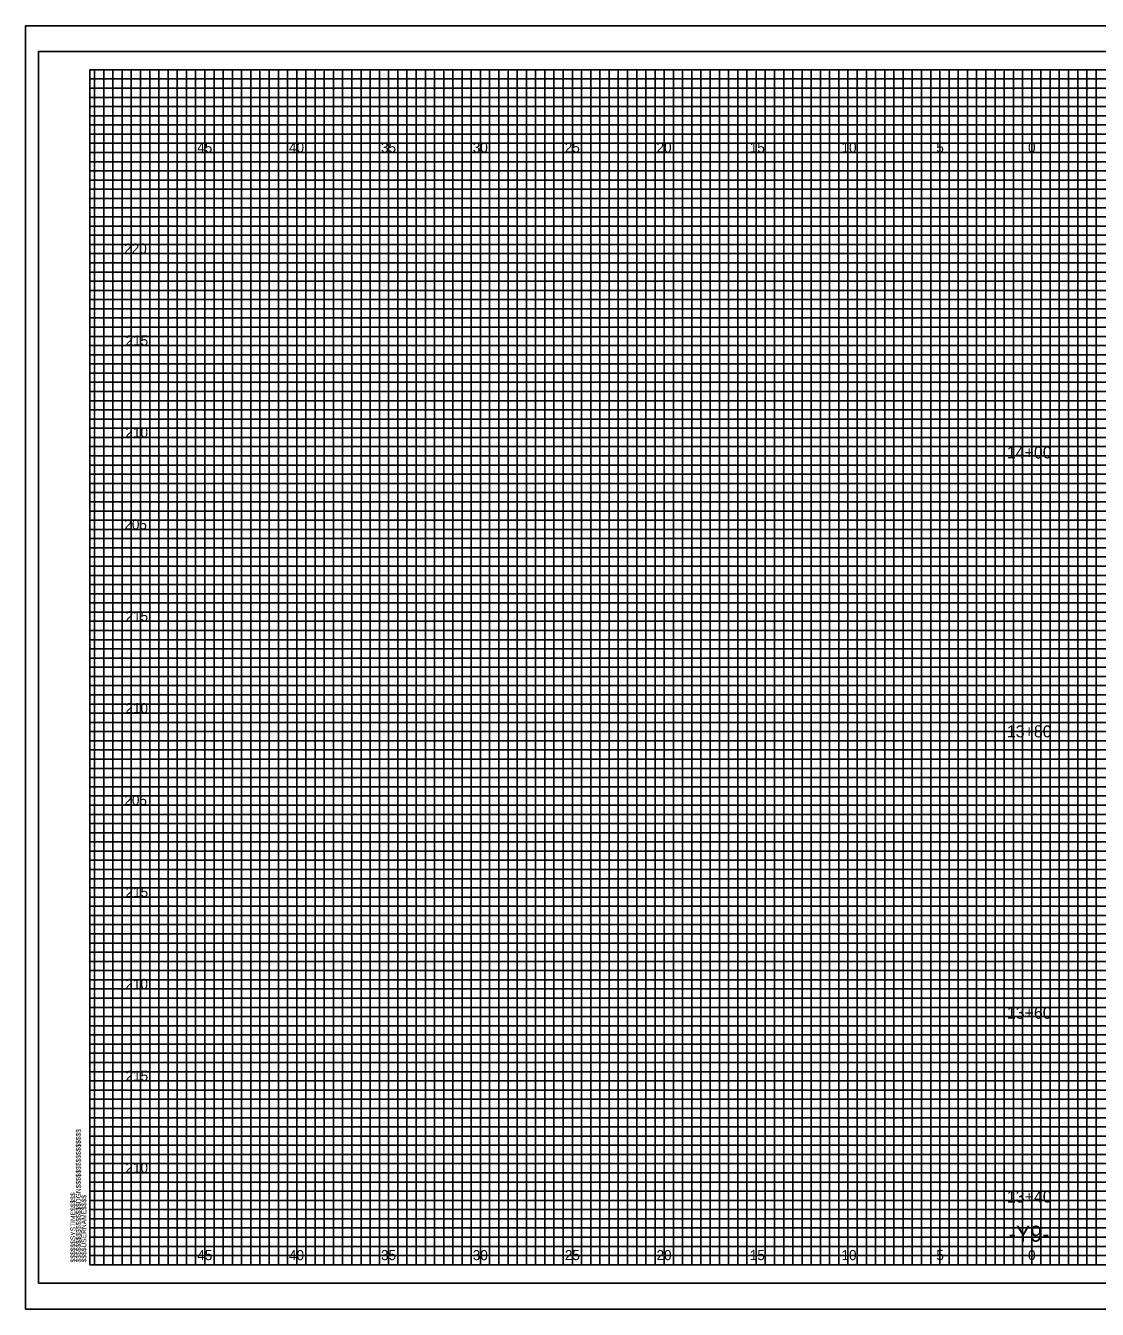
# Model space of a CAD drawing. Extents: x -4 to 103, y -2 to 492.
# Drawn here: x -3.5 to 54.8, y 210.1 to 279.9 of the extents above; entities that cross this region are included whole.
import ezdxf

# ---------------------------------------------------------------- set-up
doc = ezdxf.new("R2010")
doc.units = 0
for name, color, linetype in [('Old_Level_10', 7, 'Continuous'), ('Old_Level_16', 7, 'Continuous'), ('Old_Level_3', 7, 'Continuous'), ('Old_Level_5', 7, 'Continuous'), ('Old_Level_8', 7, 'Continuous'), ('Prop Dimension', 7, 'Continuous'), ('Prop Terminator CELL', 7, 'Continuous'), ('Prop XS Finish Grade', 7, 'Continuous'), ('Prop XS Finish Grade Earthwork', 7, 'Continuous'), ('Prop XS SE Text', 7, 'Continuous'), ('Prop XSC Text', 7, 'Continuous')]:
    doc.layers.add(name, color=color, linetype=linetype)

msp = doc.modelspace()

# ---------------------------------------------------------------- linework, layer by layer
at = {"layer": 'Old_Level_10'}
for p, q in [((1.25, 212.475), (1.25, 277.475)), ((3.75, 212.475), (3.75, 277.475)), ((6.25, 212.475), (6.25, 277.475)), ((8.75, 212.475), (8.75, 277.475)), ((11.25, 212.475), (11.25, 277.475)), ((13.75, 212.475), (13.75, 277.475)), ((16.25, 212.475), (16.25, 277.475)), ((18.75, 212.475), (18.75, 277.475)), ((21.25, 212.475), (21.25, 277.475)), ((23.75, 212.475), (23.75, 277.475)), ((26.25, 212.475), (26.25, 277.475)), ((28.75, 212.475), (28.75, 277.475)), ((31.25, 212.475), (31.25, 277.475)), ((33.75, 212.475), (33.75, 277.475)), ((36.25, 212.475), (36.25, 277.475)), ((38.75, 212.475), (38.75, 277.475)), ((41.25, 212.475), (41.25, 277.475)), ((43.75, 212.475), (43.75, 277.475)), ((46.25, 212.475), (46.25, 277.475)), ((48.75, 212.475), (48.75, 277.475)), ((51.25, 212.475), (51.25, 277.475)), ((53.75, 212.475), (53.75, 277.475)), ((0, 274.975), (74.25, 274.975)), ((0, 272.475), (102.5, 272.475)), ((0, 269.975), (102.5, 269.975)), ((0, 267.475), (102.5, 267.475)), ((0, 264.975), (102.5, 264.975)), ((0, 262.475), (102.5, 262.475)), ((0, 259.975), (102.5, 259.975)), ((0, 257.475), (102.5, 257.475)), ((0, 254.975), (102.5, 254.975)), ((0, 252.475), (102.5, 252.475)), ((0, 249.975), (102.5, 249.975)), ((0, 247.475), (102.5, 247.475)), ((0, 244.975), (102.5, 244.975)), ((0, 242.475), (102.5, 242.475)), ((0, 239.975), (102.5, 239.975)), ((0, 237.475), (102.5, 237.475)), ((0, 234.975), (102.5, 234.975)), ((0, 232.475), (102.5, 232.475)), ((0, 229.975), (102.5, 229.975)), ((0, 227.475), (102.5, 227.475)), ((0, 224.975), (102.5, 224.975)), ((0, 222.475), (102.5, 222.475)), ((0, 219.975), (102.5, 219.975)), ((0, 217.475), (102.5, 217.475)), ((0, 214.975), (102.5, 214.975))]:
    msp.add_line(p, q, dxfattribs=at)
at = {"layer": 'Old_Level_3'}
for p, q in [((-3.5, 279.875), (103.4, 279.875)), ((-3.5, 279.875), (-3.5, 210.05)), ((-3.5, 210.05), (103.4, 210.05))]:
    msp.add_line(p, q, dxfattribs=at)
at = {"layer": 'Old_Level_5'}
msp.add_lwpolyline([(103.4, 279.875), (-3.5, 279.875), (-3.5, 210.05), (103.4, 210.05)], close=True, dxfattribs=at)
at = {"layer": 'Old_Level_8'}
for points in [[(1.25, 212.475), (1.25, 277.475), (3.75, 277.475), (3.75, 212.475), (6.25, 212.475), (6.25, 277.475), (8.75, 277.475), (8.75, 212.475), (11.25, 212.475), (11.25, 277.475), (13.75, 277.475), (13.75, 212.475), (16.25, 212.475), (16.25, 277.475), (18.75, 277.475), (18.75, 212.475), (21.25, 212.475), (21.25, 277.475), (23.75, 277.475), (23.75, 212.475), (26.25, 212.475), (26.25, 277.475), (28.75, 277.475), (28.75, 212.475), (31.25, 212.475), (31.25, 277.475), (33.75, 277.475), (33.75, 212.475), (36.25, 212.475), (36.25, 277.475), (38.75, 277.475), (38.75, 212.475), (41.25, 212.475), (41.25, 277.475), (43.75, 277.475), (43.75, 212.475), (46.25, 212.475), (46.25, 277.475), (48.75, 277.475), (48.75, 212.475), (51.25, 212.475), (51.25, 277.475), (53.75, 277.475), (53.75, 212.475)], [(102.5, 272.475), (0, 272.475), (0, 274.975), (74.25, 274.975)], [(102.5, 267.475), (0, 267.475), (0, 269.975), (102.5, 269.975)], [(102.5, 262.475), (0, 262.475), (0, 264.975), (102.5, 264.975)], [(102.5, 257.475), (0, 257.475), (0, 259.975), (102.5, 259.975)], [(102.5, 252.475), (0, 252.475), (0, 254.975), (102.5, 254.975)], [(102.5, 247.475), (0, 247.475), (0, 249.975), (102.5, 249.975)], [(102.5, 242.475), (0, 242.475), (0, 244.975), (102.5, 244.975)], [(102.5, 237.475), (0, 237.475), (0, 239.975), (102.5, 239.975)], [(102.5, 232.475), (0, 232.475), (0, 234.975), (102.5, 234.975)], [(102.5, 227.475), (0, 227.475), (0, 229.975), (102.5, 229.975)], [(102.5, 222.475), (0, 222.475), (0, 224.975), (102.5, 224.975)], [(102.5, 217.475), (0, 217.475), (0, 219.975), (102.5, 219.975)], [(0, 214.975), (102.5, 214.975)]]:
    msp.add_lwpolyline(points, dxfattribs=at)
at = {"layer": 'Prop Dimension'}
for points in [[(0.25, 212.475), (0.25, 277.475), (0.75, 277.475), (0.75, 212.475), (1.75, 212.475), (1.75, 277.475), (2.25, 277.475), (2.25, 212.475), (2.75, 212.475), (2.75, 277.475), (3.25, 277.475), (3.25, 212.475), (4.25, 212.475), (4.25, 277.475), (4.75, 277.475), (4.75, 212.475), (5.25, 212.475), (5.25, 277.475), (5.75, 277.475), (5.75, 212.475), (6.75, 212.475), (6.75, 277.475), (7.25, 277.475), (7.25, 212.475), (7.75, 212.475), (7.75, 277.475), (8.25, 277.475), (8.25, 212.475), (9.25, 212.475), (9.25, 277.475), (9.75, 277.475), (9.75, 212.475), (10.25, 212.475), (10.25, 277.475), (10.75, 277.475), (10.75, 212.475), (11.75, 212.475), (11.75, 277.475), (12.25, 277.475), (12.25, 212.475), (12.75, 212.475), (12.75, 277.475), (13.25, 277.475), (13.25, 212.475), (14.25, 212.475), (14.25, 277.475), (14.75, 277.475), (14.75, 212.475), (15.75, 212.475), (15.25, 212.475), (15.25, 277.475), (15.75, 277.475), (15.75, 212.475), (16.75, 212.475), (16.75, 277.475), (17.25, 277.475), (17.25, 212.475), (17.75, 212.475), (17.75, 277.475), (18.25, 277.475), (18.25, 212.475), (19.25, 212.475), (19.25, 277.475), (19.75, 277.475), (19.75, 212.475), (20.25, 212.475), (20.25, 277.475), (20.75, 277.475), (20.75, 212.475), (21.75, 212.475), (21.75, 277.475), (22.25, 277.475), (22.25, 212.475), (22.75, 212.475), (22.75, 277.475), (23.25, 277.475), (23.25, 212.475), (24.25, 212.475), (24.25, 277.475), (24.75, 277.475), (24.75, 212.475), (25.25, 212.475), (25.25, 277.475), (25.75, 277.475), (25.75, 212.475), (26.75, 212.475), (26.75, 277.475), (27.25, 277.475), (27.25, 212.475), (27.75, 212.475), (27.75, 277.475), (28.25, 277.475), (28.25, 212.475), (29.25, 212.475), (29.25, 277.475), (29.75, 277.475), (29.75, 212.475), (30.25, 212.475), (30.25, 277.475), (30.75, 277.475), (30.75, 212.475)], [(30.75, 212.475), (31.75, 212.475), (31.75, 277.475), (32.25, 277.475), (32.25, 212.475), (32.75, 212.475), (32.75, 277.475), (33.25, 277.475), (33.25, 212.475), (34.25, 212.475), (34.25, 277.475), (34.75, 277.475), (34.75, 212.475), (35.25, 212.475), (35.25, 277.475), (35.75, 277.475), (35.75, 212.475), (36.75, 212.475), (36.75, 277.475), (37.25, 277.475), (37.25, 212.475), (37.75, 212.475), (37.75, 277.475), (37.75, 212.475)], [(38.25, 277.475), (38.25, 212.475), (39.25, 212.475), (39.25, 277.475), (39.75, 277.475), (39.75, 212.475), (40.25, 212.475), (40.25, 277.475), (40.75, 277.475), (40.75, 212.475), (41.75, 212.475), (41.75, 277.475), (42.25, 277.475), (42.25, 212.475), (42.75, 212.475), (42.75, 277.475), (43.25, 277.475), (43.25, 212.475), (43.75, 212.475), (44.25, 212.475), (44.25, 277.475), (44.75, 277.475), (44.75, 212.475), (45.25, 212.475), (45.25, 277.475), (45.75, 277.475), (45.75, 212.475), (46.75, 212.475), (46.75, 277.475), (47.25, 277.475), (47.25, 212.475), (47.75, 212.475), (47.75, 277.475), (48.25, 277.475), (48.25, 212.475), (49.25, 212.475), (49.25, 277.475), (49.75, 277.475), (49.75, 212.475), (50.25, 212.475), (50.25, 277.475), (50.75, 277.475), (50.75, 212.475), (51.75, 212.475), (51.75, 277.475), (52.25, 277.475), (52.25, 212.475), (52.75, 212.475), (52.75, 277.475), (53.25, 277.475), (53.25, 212.475), (54.25, 212.475), (54.25, 277.475), (54.75, 277.475), (54.75, 212.475), (55.25, 212.475)], [(0, 274.475), (0, 275.475), (74.25, 275.475), (74.25, 275.975), (0, 275.975), (0, 276.475), (74.25, 276.475), (74.25, 276.975), (0, 276.975)], [(102.5, 274.475), (0, 274.475)], [(102.5, 273.475), (0, 273.475), (0, 273.975), (102.5, 273.975)], [(102.5, 271.975), (0, 271.975), (0, 272.975), (102.5, 272.975)], [(102.5, 270.975), (0, 270.975), (0, 271.475), (102.5, 271.475)], [(102.5, 269.475), (0, 269.475), (0, 270.475), (102.5, 270.475)], [(102.5, 268.475), (0, 268.475), (0, 268.975), (102.5, 268.975)], [(102.5, 266.975), (0, 266.975), (0, 267.975), (102.5, 267.975)], [(102.5, 265.975), (0, 265.975), (0, 266.475), (102.5, 266.475)], [(0, 265.475), (102.5, 265.475)], [(102.5, 264.475), (0, 264.475)], [(102.5, 263.475), (0, 263.475), (0, 263.975), (102.5, 263.975)], [(102.5, 261.975), (0, 261.975), (0, 262.975), (102.5, 262.975)], [(102.5, 260.975), (0, 260.975), (0, 261.475), (102.5, 261.475)], [(102.5, 259.475), (0, 259.475), (0, 260.475), (102.5, 260.475)], [(102.5, 258.475), (0, 258.475), (0, 258.975), (102.5, 258.975)], [(102.5, 256.975), (0, 256.975), (0, 257.975), (102.5, 257.975)], [(102.5, 255.975), (0, 255.975), (0, 256.475), (102.5, 256.475)], [(102.5, 254.475), (0, 254.475), (0, 255.475), (102.5, 255.475)], [(102.5, 253.475), (0, 253.475), (0, 253.975), (102.5, 253.975)], [(102.5, 251.975), (0, 251.975), (0, 252.975), (102.5, 252.975)], [(102.5, 250.975), (0, 250.975), (0, 251.475), (102.5, 251.475)], [(102.5, 249.475), (0, 249.475), (0, 250.475), (102.5, 250.475)], [(102.5, 248.475), (0, 248.475), (0, 248.975), (102.5, 248.975)], [(102.5, 246.975), (0, 246.975), (0, 247.975), (102.5, 247.975)], [(102.5, 245.975), (0, 245.975), (0, 246.475), (102.5, 246.475)], [(102.5, 244.475), (0, 244.475), (0, 245.475), (102.5, 245.475)], [(102.5, 243.475), (0, 243.475), (0, 243.975)], [(0, 243.975), (102.5, 243.975)], [(102.5, 241.975), (0, 241.975), (0, 242.975), (102.5, 242.975)], [(102.5, 240.975), (0, 240.975), (0, 241.475), (102.5, 241.475)], [(102.5, 239.475), (0, 239.475), (0, 240.475), (102.5, 240.475)], [(102.5, 238.475), (0, 238.475), (0, 238.975), (102.5, 238.975)], [(102.5, 236.975), (0, 236.975), (0, 237.975), (102.5, 237.975)], [(102.5, 235.975), (0, 235.975), (0, 236.475), (102.5, 236.475)], [(102.5, 234.475), (0, 234.475), (0, 235.475), (102.5, 235.475)], [(102.5, 233.475), (0, 233.475), (0, 233.975), (102.5, 233.975)], [(102.5, 231.975), (0, 231.975), (0, 232.975), (102.5, 232.975)], [(102.5, 230.975), (0, 230.975), (0, 231.475), (102.5, 231.475)], [(102.5, 229.475), (0, 229.475), (0, 230.475), (102.5, 230.475)], [(102.5, 228.475), (0, 228.475), (0, 228.975), (102.5, 228.975)], [(102.5, 226.975), (0, 226.975), (0, 227.975), (102.5, 227.975)], [(102.5, 225.975), (0, 225.975), (0, 226.475), (102.5, 226.475)], [(102.5, 224.475), (0, 224.475), (0, 225.475), (102.5, 225.475)], [(102.5, 223.475), (0, 223.475), (0, 223.975), (102.5, 223.975)], [(102.5, 221.975), (0, 221.975), (0, 222.975), (102.5, 222.975)], [(102.5, 220.975), (0, 220.975), (0, 221.475), (102.5, 221.475)], [(102.5, 219.475), (0, 219.475), (0, 220.475), (102.5, 220.475)], [(102.5, 218.475), (0, 218.475), (0, 218.975), (102.5, 218.975)], [(102.5, 216.975), (0, 216.975), (0, 217.975), (102.5, 217.975)], [(102.5, 215.975), (0, 215.975), (0, 216.475), (102.5, 216.475)], [(102.5, 214.475), (0, 214.475), (0, 215.475), (102.5, 215.475)], [(102.5, 213.475), (0, 213.475), (0, 213.975), (102.5, 213.975)], [(0, 212.975), (102.5, 212.975)]]:
    msp.add_lwpolyline(points, dxfattribs=at)
at = {"layer": 'Prop XS SE Text'}
msp.add_lwpolyline([(103, 278.475), (-2.8, 278.475), (-2.8, 211.475), (103, 211.475)], close=True, dxfattribs=at)
at = {"layer": 'Prop XSC Text'}
msp.add_lwpolyline([(102.5, 277.475), (0, 277.475), (0, 212.475), (102.5, 212.475)], close=True, dxfattribs=at)

# ---------------------------------------------------------------- texts
at = {"layer": 'Old_Level_16'}
for s, p in [('45', (5.8399, 272.975)), ('40', (10.8313, 272.975)), ('35', (15.8399, 272.975)), ('30', (20.8313, 272.975)), ('25', (25.8399, 272.975)), ('20', (30.8313, 272.975)), ('15', (35.9058, 272.975)), ('10', (40.8971, 272.975)), ('5', (46.0574, 272.975)), ('0', (51.0488, 272.975)), ('0', (51.0488, 272.975)), ('45', (5.8399, 212.725)), ('40', (10.8313, 212.725)), ('35', (15.8399, 212.725)), ('30', (20.8313, 212.725)), ('25', (25.8399, 212.725)), ('20', (30.8313, 212.725)), ('15', (35.9058, 212.725)), ('10', (40.8971, 212.725)), ('5', (46.0574, 212.725)), ('0', (51.0488, 212.725)), ('0', (51.0488, 212.725))]:
    msp.add_text(s, height=0.55, dxfattribs=at).set_placement(p)
at = {"layer": 'Old_Level_8'}
msp.add_text('040397', height=0.0025, rotation=90, dxfattribs=at).set_placement((-0.0007, 277.4614))
at = {"layer": 'Prop Terminator CELL'}
msp.add_text('-Y9-', height=0.875, dxfattribs=at).set_placement((49.9985, 213.725))
at = {"layer": 'Prop XS Finish Grade'}
for s, p in [('14+00', (49.8934, 256.3349)), ('13+80', (49.8934, 241.162)), ('13+60', (49.8934, 225.8557)), ('13+40', (49.8934, 215.8552))]:
    msp.add_text(s, height=0.65, dxfattribs=at).set_placement(p)
at = {"layer": 'Prop XS Finish Grade Earthwork'}
for s, p in [('220', (1.8638, 267.475)), ('215', (1.9383, 262.475)), ('210', (1.9296, 257.475)), ('205', (1.8724, 252.475)), ('215', (1.9383, 247.475)), ('210', (1.9296, 242.475)), ('205', (1.8724, 237.475)), ('215', (1.9383, 232.475)), ('210', (1.9296, 227.475)), ('215', (1.9383, 222.475)), ('210', (1.9296, 217.475))]:
    msp.add_text(s, height=0.55, dxfattribs=at).set_placement(p)
at = {"layer": 'Prop XSC Text'}
for s, p in [('$$$$$$$$$$$$$$$$DGN$$$$$$$$$$$$$$$$', (-0.5, 212.6)), ('$$$$$$SYSTIME$$$$$', (-0.7973, 212.5997)), ('$$$$USERNAME$$$$', (-0.2, 212.6))]:
    msp.add_text(s, height=0.2625, rotation=90, dxfattribs=at).set_placement(p)

doc.saveas('drawing.dxf')
